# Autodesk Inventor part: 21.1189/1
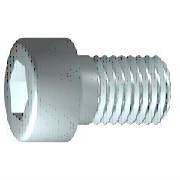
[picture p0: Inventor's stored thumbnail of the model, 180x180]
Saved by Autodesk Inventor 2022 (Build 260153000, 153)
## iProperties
Created: 2006-02
Part Number: 21.1189/1
Material: Stainless Steel
Description: M8X25 POWER-LOCK SCREW SS
Document SubType Name: Modeling
Standard: DIN 7984
Designer: Andy Moles
Standards Organization: DIN
Language: en-US
Size Designation: M8 x 25
Categories: <MemberInstance><Categories><Category DisplayName="Fasteners" InternalName="e4da775c-781d-43d5-af7c-5136215cf5a6" Mnemonic="FSTN"><Category DisplayName="Bolts"
Density: 8 g/cm^3
Mass: 13.2957 g
Surface Area: 10.8236 cm^2
Volume: 1.66196 cm^3
Vendor: S
Appearance: Light Gray
Stock Number: 21.1189_1 POWER-LOCK SCREW SS
Author: Andy Moles
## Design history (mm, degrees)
sketch "Sketch1"
  geometry: L1 (1.167, 0)-(25, 0); L2 (25, 0)-(25, 4); L3 (25, 4)-(1, 4); L4 (1, 4)-(0.233, 4); L5 (0.233, 4)-(0, 4); L6 (0, 4)-(0, 6.7); L7 (0, 6.7)-(-0.8, 6.7); L8 (-4.3, 3.2)-(-4.3, 2.887); L9 (-4.3, 2.887)-(-0.5, 2.887); L10 (-0.5, 2.887)-(1.167, 0); L11 (-11.03, 0)-(31.005, 0) reference; L12 (0, -1.485)-(0, 8.91) reference; L13 (1, 4)-(0, 4); A1 r 3.5 centre (-0.8, 3.2) between (-0.8, 6.7) and (-4.3, 3.2); 1 further point
  constraints: 22 end point, 6 parallel, 3 point on line, 2 collinear, 2 perpendicular, 2 point on circle, 2 tangent, 1 centre point, 1 horizontal
  dimensions: "d1" = 24 distance from line of L3.end L2 (= GEL); "d2" = 0.76691 distance of L4.end L3.end (computed from GAL); "d5" = 60 deg angle of L10 L1; "d6" = 8 diameter of L3 L1 (= GD); "d7" = 8 diameter of L5 L1 (= BDM); "d8" = 5.7735 diameter of L9 L1 (= 1.1547 x SW); "d26" = 25 distance between parallel lines of L12 L2 (= NLG); "d30" = 3.8 distance of L8.end L9.end; "d31" = 3.5 radius of A1; "d32" = 4.3 distance from line of L6 L8.end; "d33" = 13.4 diameter of L7 L1
revolve "Body" sketch "Sketch1" stored, may be unused: angle "d10" = 90 deg
sketch "Sketch2"
  geometry: L1 (0, -9.38)-(0, 9.38) reference; L2 (-9.38, 0)-(9.38, 0) reference; L3 (2.887, 0)-(1.443, -2.5); L4 (1.443, -2.5)-(-1.443, -2.5); L5 (-1.443, -2.5)-(-2.887, 0); L6 (-2.887, 0)-(-1.443, 2.5); L7 (-1.443, 2.5)-(1.443, 2.5); L8 (1.443, 2.5)-(2.887, 0); 2 further points
  constraints: 12 end point, 1 coincident, 1 horizontal alignment, 1 point on line, 12 other
extrude "Slot" join sketch "Sketch2" stored distance "d11" = 10; taper "d12" = 0 deg
workplane "Work Plane1"
body "Solid1"
feature "Thread" dims "d13" = 24 (= GEL), "d14" = 0
chamfer "Chamfer1" distance "d15" = 0.76681 (= -0.5 x SPD + 0.5 x GD); stored, may be unused: second distance "d16" = 0.76681 (= GUL), angle "d27" = 45 deg
other parameters: "GD" = 8 (= NND) [user parameter; used in 2 equation terms], "NLG" = 25 [user parameter; used in 1 equation term], "GEL" = 24 [user parameter; used in 2 equation terms], "KOD" = 13 [user parameter], "KOH" = 5 [user parameter], "INTI" = 3.8 [user parameter], "GAL" = 0.76681 (= 0.61345 x PTC) [user parameter; used in 1 equation term], "GUL" = 0.76681 (= 0.61345 x PTC) [user parameter; used in 1 equation term], "BDM" = 8 (= NND) [user parameter; used in 1 equation term], "SW" = 5 [user parameter; used in 2 equation terms], "RR" = 0.8 [user parameter], "SPD" = 6.46637 (= NND - 1.2269 x PTC) [user parameter; used in 1 equation term], "d19" = 0, "d28" = 0, "d29" = 0, "TOA" = 30 deg [user parameter], "GD1" = 6.46637 (= THREADDIA - 1.2269 x PTC) [user parameter], "THREADDIA" = 8 [user parameter; used in 1 equation term], "FAWI" = 45 deg [user parameter], "ANG" = 120 deg [user parameter], "TPU" = 8 (computed from PTC) [user parameter], "PTC" = 1.25 [user parameter; used in 5 equation terms], "NND" = 8 [user parameter; used in 3 equation terms], "E0" = 5.775 (= 1.155 x SW) [user parameter]
